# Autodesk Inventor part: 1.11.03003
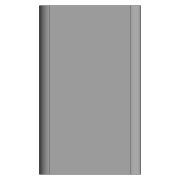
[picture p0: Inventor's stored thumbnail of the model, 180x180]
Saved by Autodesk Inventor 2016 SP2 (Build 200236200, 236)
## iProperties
Company: CAD Team Handzik
Created: 2017-10
Part Number: 1.11.03003
Material: Allgemein
Document SubType Name: Modellieren
Designer: CAD Team Handzik
Appearance: Allgemein
Vendor: Item
MT_KOPF: =<CPR_ZEICHNR> - <CPR_SHORT>
Author: CAD Team Handzik
Revision Number: ANY
Subject: Muster für iPart Modul
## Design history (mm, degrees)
workplane "Arbeitsebene1"
sketch "Skizze1"
  geometry: L1 (0, 0)-(24, 0); L2 (27, 3)-(27, 27); L3 (24, 30)-(0, 30); L4 (-3, 27)-(-3, 3); L5 (22.179, 27.8)-(1.821, 27.8); L6 (17.568, 21.982)-(22.532, 26.946); L7 (1.468, 26.946)-(6.432, 21.982); L8 (23.946, 25.532)-(18.982, 20.568); L9 (24.8, 4.821)-(24.8, 25.179); L10 (18.982, 9.432)-(23.946, 4.468); L11 (6.432, 8.018)-(1.468, 3.054); L12 (22.532, 3.054)-(17.568, 8.018); L13 (1.821, 2.2)-(22.179, 2.2); L14 (5.018, 20.568)-(0.054, 25.532); L15 (0.054, 4.468)-(5.018, 9.432); L16 (-0.8, 25.179)-(-0.8, 4.821); C1 r 6 at (12, 15); A1 r 3 centre (0, 3) between (-3, 3) and (0, 0); A2 r 3 centre (24, 3) between (24, 0) and (27, 3); A3 r 3 centre (24, 27) between (27, 27) and (24, 30); A4 r 3 centre (0, 27) between (0, 30) and (-3, 27); A5 r 0.5 centre (1.821, 27.3) between (1.821, 27.8) and (1.468, 26.946); A6 r 0.5 centre (22.179, 27.3) between (22.532, 26.946) and (22.179, 27.8); A7 r 0.5 centre (17.214, 22.336) between (16.925, 21.928) and (17.568, 21.982); A8 r 8.5 centre (12, 15) between (16.925, 21.928) and (7.075, 21.928); A9 r 0.5 centre (6.786, 22.336) between (6.432, 21.982) and (7.075, 21.928); A10 r 8.5 centre (12, 15) between (18.928, 10.075) and (18.928, 19.925); A11 r 0.5 centre (19.336, 20.214) between (18.982, 20.568) and (18.928, 19.925); A12 r 0.5 centre (24.3, 25.179) between (24.8, 25.179) and (23.946, 25.532); A13 r 0.5 centre (24.3, 4.821) between (23.946, 4.468) and (24.8, 4.821); A14 r 0.5 centre (19.336, 9.786) between (18.928, 10.075) and (18.982, 9.432); A15 r 0.5 centre (1.821, 2.7) between (1.468, 3.054) and (1.821, 2.2); A16 r 0.5 centre (6.786, 7.664) between (7.075, 8.072) and (6.432, 8.018); A17 r 8.5 centre (12, 15) between (7.075, 8.072) and (16.925, 8.072); A18 r 0.5 centre (17.214, 7.664) between (17.568, 8.018) and (16.925, 8.072); A19 r 0.5 centre (22.179, 2.7) between (22.179, 2.2) and (22.532, 3.054); A20 r 0.5 centre (-0.3, 25.179) between (0.054, 25.532) and (-0.8, 25.179); A21 r 0.5 centre (4.664, 20.214) between (5.072, 19.925) and (5.018, 20.568); A22 r 8.5 centre (12, 15) between (5.072, 19.925) and (5.072, 10.075); A23 r 0.5 centre (4.664, 9.786) between (5.018, 9.432) and (5.072, 10.075); A24 r 0.5 centre (-0.3, 4.821) between (-0.8, 4.821) and (0.054, 4.468); 1 further point
  constraints: 48 point on circle, 32 end point, 25 centre point
workplane "Arbeitsebene2"
workplane "Arbeitsebene3"
extrude "Extrusion1" new body sketch "Skizze1" stored distance "d2" = 10; taper "d3" = 0 deg
node "Volumenkörper2"
node "Volumenkörper"
node "Flächenkörper"
other parameters: "d0" = 25 (= 0.5 x LANG), "d1" = -25 (= -0.5 x LANG)
